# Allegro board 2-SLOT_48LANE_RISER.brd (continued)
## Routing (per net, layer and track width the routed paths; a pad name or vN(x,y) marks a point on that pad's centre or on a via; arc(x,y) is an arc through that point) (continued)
PE_SLOT2_RX_DN<11>: length 111.2
  IN2 w0.089: 142.12,92.72 142.09,92.75 141.07,92.75 141.03,92.7 140.98,92.66 140.63,92.66 140.58,92.7 140.54,92.75 140.18,92.75 140.14,92.7 140.09,92.66 139.74,92.66 139.69,92.7 139.65,92.75 138.88,92.75 v5(138.49,92.36)
  IN2 w0.145: 142.12,92.72 142.13,92.72 143.21,92.91 144.53,92.68 147.87,93.27 148,93.18 148.72,93.31 148.83,93.47 149.35,93.56 149.53,93.43 150.21,93.56 150.34,93.73 150.86,93.83 151.02,93.71 151.73,93.84 151.84,94 152.39,94.1 156.86,93.31 161.44,94.14 161.66,94.18 167.56,93.14 168.39,92.55 169.17,92.42 169.25,92.31 169.9,92.19 170.01,92.27 185.24,89.58 194.7,91.25 195.12,91.18 196.8,90.88 196.9,90.74 197.57,90.62 197.71,90.72 198.28,90.62 198.37,90.5 199.07,90.38 199.19,90.46 199.76,90.36 199.86,90.21 200.52,90.1 200.67,90.2 201.24,90.1 201.35,89.93 201.98,89.82 202.14,89.94 206.35,89.2 211.63,90.13 218.05,89 218.18,88.81 218.84,88.7 219.02,88.83 219.59,88.73 219.7,88.57 220.41,88.45 220.56,88.55 221.13,88.45 221.24,88.3 221.94,88.17 222.1,88.28 222.67,88.18 222.77,88.04 223.5,87.91 223.64,88.01 224.21,87.91 224.32,87.75 225.02,87.63 225.18,87.74 226.84,87.45 228.7,86.15 229.67,84.77 229.67,82.54 230.02,82.18 231.79,82.18 231.93,82.04 231.93,81.67 231.79,81.53 230.13,81.53 229.69,81.1 229.69,79.87 230.68,78.88 230.68,75.3 230.54,75.16 230.4,75.08 230.2,75.15 J2.A65
  BOTTOM w0.135: U1.D19 v5(138.49,92.36)
PE_SLOT2_RX_DN<12>: length 103.4
  IN2 w0.089: v5(138.49,90.76) 138.7,90.97 139.7,90.97 140.18,91.05 141.09,91.69 141.72,91.69 142.25,91.33 143.22,91.33 143.26,91.28 143.28,91.28
  IN2 w0.145: J2.A69 226.2,75.15 226.4,75.08 226.54,75.16 226.68,75.3 226.68,78.88 225.69,79.87 225.69,81.12 225.96,82.63 225.49,85.25 224.75,86.31 224.75,86.31 224.01,86.83 221.34,87.3 221.2,87.2 220.56,87.31 220.47,87.45 219.9,87.55 219.75,87.45 219.13,87.56 219.03,87.7 218.46,87.81 218.33,87.71 217.68,87.83 217.59,87.96 217.02,88.06 216.87,87.96 216.25,88.07 216.15,88.21 215.58,88.31 215.44,88.22 214.8,88.33 214.71,88.47 211.17,89.09 205.94,88.17 204.56,88.41 204.45,88.33 203.72,88.46 203.64,88.57 203.07,88.67 202.95,88.59 202.23,88.72 202.15,88.84 201.58,88.94 201.45,88.85 200.75,88.97 200.65,89.1 200.08,89.2 199.97,89.12 199.24,89.25 199.16,89.36 198.59,89.46 198.48,89.38 197.75,89.51 197.67,89.63 197.1,89.73 196.95,89.62 196.34,89.73 196.24,89.88 194.6,90.17 185.14,88.5 167.86,91.55 167.16,92.04 161.41,93.06 159.89,92.79 159.78,92.64 159.11,92.52 158.96,92.62 158.39,92.52 158.3,92.4 157.59,92.27 157.46,92.36 156.84,92.25 153.24,92.89 149.28,92.19 149.21,92.08 148.52,91.96 148.41,92.04 147.84,91.93 147.76,91.81 147.09,91.7 146.97,91.78 146.4,91.68 146.3,91.54 145.66,91.43 145.53,91.53 144.14,91.28 143.28,91.28
  BOTTOM w0.135: U1.D17 v5(138.49,90.76)
PE_SLOT2_RX_DN<13>: length 101.5
  IN2 w0.089: v5(138.49,89.96) 138.88,90.35 141.78,90.35 141.83,90.3 141.85,90.3
  IN2 w0.145: J2.A73 222.2,75.15 222.4,75.08 222.54,75.16 222.68,75.3 222.68,78.88 221.71,79.86 221.71,82.28 221.16,85.36 220.83,85.83 220.06,86.37 218.85,86.58 218.84,86.58 218.69,86.48 218.12,86.58 218.01,86.73 217.56,86.81 217.55,86.8 217.38,86.68 216.85,86.78 216.72,86.96 216.28,87.04 216.27,87.03 216.11,86.92 215.55,87.02 215.44,87.19 214.99,87.27 214.98,87.26 214.81,87.14 214.27,87.24 214.15,87.41 213.71,87.49 213.56,87.39 212.97,87.5 212.86,87.64 212.42,87.72 212.27,87.61 211.69,87.71 211.58,87.87 210.52,88.05 205.36,87.14 200.11,88.07 199.99,87.99 199.47,88.08 199.39,88.2 198.96,88.27 198.83,88.18 198.34,88.27 198.25,88.4 197.82,88.47 197.72,88.4 197.18,88.49 197.11,88.6 196.68,88.67 196.58,88.6 196.04,88.69 195.97,88.8 194.13,89.12 194.03,89.14 184.88,87.53 173.19,89.59 172.97,89.43 172.89,88.97 172.48,88.68 171.99,88.77 171.7,89.18 171.78,89.64 171.62,89.86 171.36,89.91 171.14,89.76 171.05,89.29 170.64,89 170.15,89.09 169.86,89.5 169.94,89.97 169.79,90.19 167.35,90.62 166.4,91.29 161.99,92.06 160.11,91.73 160.01,91.59 159.32,91.47 159.17,91.57 158.56,91.46 158.46,91.32 157.76,91.19 157.63,91.29 156.92,91.17 153.62,91.75 150.4,91.18 150.31,91.05 149.66,90.93 149.52,91.03 148.95,90.93 148.89,90.83 148.17,90.7 148.08,90.77 147.51,90.67 147.43,90.56 146.74,90.44 146.63,90.52 146.06,90.42 145.97,90.29 145.3,90.17 145.18,90.26 144.23,90.09 143.03,90.3 141.85,90.3
  BOTTOM w0.135: U1.D16 v5(138.49,89.96)
PE_SLOT2_RX_DN<14>: length 92.5
  IN2 w0.089: 141.73,89.25 141.72,89.25 141.71,89.26 141.68,89.3 141.19,89.39 140.6,89.24 139.75,88.65 139.31,88.57 138.7,88.57 v5(138.49,88.36)
  IN2 w0.145: J2.A77 218.2,75.15 218.4,75.08 218.54,75.16 218.68,75.3 218.68,78.88 217.7,79.86 217.7,80.52 217.55,81.36 217.12,81.97 216.16,82.65 216.03,82.7 216.02,82.7 214.91,83.17 212.8,84.64 212.8,84.65 210.82,85 210.7,84.91 210.01,85.03 209.92,85.15 209.35,85.25 209.25,85.18 208.52,85.31 208.45,85.41 207.88,85.51 207.79,85.45 207.05,85.58 206.98,85.67 204.62,86.09 204.52,86.02 203.83,86.14 203.76,86.24 203.19,86.34 203.07,86.26 202.41,86.37 202.33,86.49 201.76,86.59 201.66,86.52 200.96,86.65 200.89,86.74 200.32,86.85 200.22,86.77 199.53,86.9 199.46,87 198.89,87.1 198.82,87.05 198.08,87.18 198.03,87.25 197.46,87.35 197.37,87.29 196.66,87.42 196.6,87.5 196.03,87.6 195.92,87.53 195.24,87.65 195.17,87.75 193.66,88.02 190.4,87.44 189.62,86.33 185,85.51 170.04,88.15 167.95,89.61 164.95,90.14 164.83,90.06 164.27,90.16 164.18,90.28 163.28,90.44 163.17,90.36 162.54,90.47 162.47,90.58 161.48,90.75 161.28,90.75 161.27,90.75 161.13,90.75 156.86,90 153.35,90.62 151.63,90.31 151.55,90.2 150.96,90.1 150.85,90.18 150.49,90.11 150.39,89.97 149.85,89.88 149.71,89.97 149.35,89.91 149.24,89.75 148.73,89.66 148.57,89.77 148.21,89.71 148.11,89.57 147.57,89.48 147.43,89.57 147.07,89.51 146.98,89.39 146.41,89.29 146.29,89.37 145.93,89.31 145.82,89.16 145.3,89.06 145.15,89.17 144.15,88.99 143.28,89.09 141.73,89.25
  BOTTOM w0.135: U1.D14 v5(138.49,88.36)
PE_SLOT2_RX_DN<15>: length 90.1
  IN2 w0.089: 142.3,87.9 142.27,87.9 142.23,87.95 141.52,87.95 141.47,87.9 141.42,87.85 141.03,87.85 140.98,87.9 140.93,87.95 140.54,87.95 140.49,87.9 140.44,87.85 140.05,87.85 140,87.9 139.95,87.95 138.88,87.95 v5(138.49,87.56)
  IN2 w0.145: J2.A81 214.2,75.15 214.4,75.08 214.54,75.16 214.68,75.3 214.68,78.88 213.67,79.89 213.67,81.36 213.54,82.06 212.79,83.13 211.98,83.7 208.63,84.29 208.54,84.23 207.97,84.33 207.91,84.42 207.49,84.49 207.38,84.41 206.84,84.51 206.76,84.62 206.35,84.69 206.25,84.62 205.7,84.72 205.62,84.82 205.21,84.89 205.1,84.82 204.56,84.91 204.48,85.02 204.07,85.1 203.95,85.01 203.42,85.11 203.34,85.22 202.93,85.3 202.81,85.22 202.28,85.31 202.2,85.42 201.79,85.5 201.65,85.4 201.16,85.48 201.06,85.63 198.12,86.14 193,85.32 192.65,85.57 190.24,85.18 189.99,84.83 186.8,84.32 172.11,86.91 171.99,86.82 171.46,86.91 171.37,87.04 170.62,87.17 170.51,87.1 169.96,87.19 169.88,87.3 169.32,87.4 168.51,87.97 167.8,88.46 165.66,88.84 165.44,88.69 165.31,87.97 164.9,87.68 164.4,87.77 164.12,88.18 164.24,88.9 164.09,89.12 162.06,89.48 161.87,89.47 161.86,89.47 161.86,89.47 161.72,89.47 160.93,89.47 160.03,89.31 159.94,89.19 159.27,89.07 159.15,89.15 158.57,89.05 158.48,88.92 157.82,88.8 157.69,88.9 156.72,88.72 153.21,89.34 150.9,88.94 150.82,88.82 150.3,88.73 150.18,88.81 149.76,88.73 149.69,88.63 149.15,88.53 149.04,88.61 148.62,88.53 148.54,88.42 148.02,88.32 147.9,88.41 147.48,88.33 147.4,88.21 146.88,88.12 146.76,88.21 146.34,88.13 146.25,88.01 145.74,87.92 145.62,88 144.34,87.78 142.74,87.9 142.74,87.9 142.3,87.9
  BOTTOM w0.135: U1.D13 v5(138.49,87.56)
PE_SLOT2_RX_DP<0>: length 181
  IN2 w0.089: 126.09,96.01 126.09,95.98 126.12,95.94 126.11,95.8 126.11,92.74 v5(126.49,92.36)
  IN2 w0.145: 126.09,96.01 126.22,97.49 126.38,99.25 126.38,99.25 126.42,99.71 129.14,103.59 132.59,106.01 137.47,106.87 141.74,109.86 151.92,111.65 152.06,111.65 152.07,111.65 153.74,111.65 165.35,109.6 167.5,108.1 173.46,103.93 190.58,100.91 194.05,101.52 206.66,99.29 212.11,100.25 272.94,89.53 272.94,89.53 273.77,89.38 276.02,87.95 277.98,85.14 278.35,83.07 277.95,80.82 277.95,79.96 278.94,78.98 278.94,75.16 278.7,74.93 278.52,74.84 278.46,74.64 J2.A16
  BOTTOM w0.135: U1.V19 v5(126.49,92.36)
PE_SLOT2_RX_DP<1>: length 180.4
  IN2 w0.089: v5(127.29,92.36) 126.91,92.74 126.91,93.47 126.67,93.71 126.67,94.24 127.22,95.02 127.27,95.14 127.25,95.2 127.26,95.22
  IN2 w0.145: 127.26,95.22 127.3,95.33 127.4,95.91 127.32,96.39 127.95,99.98 129.65,102.41 132.94,104.71 144.49,106.75 145.55,106.56 145.82,106.75 146.08,108.23 146.44,108.48 147.03,108.38 147.28,108.02 147.02,106.54 147.17,106.32 147.44,106.27 147.66,106.42 147.92,107.91 148.28,108.16 148.86,108.06 149.11,107.7 148.85,106.21 149.01,105.99 152.28,105.41 152.28,105.42 162.9,107.29 168.39,106.32 173.01,103.08 190.63,99.98 194.35,100.63 206.77,98.44 212.25,99.41 267.6,89.65 270.47,89.15 273.25,87.2 273.8,86.42 273.94,85.6 273.94,79.76 272.97,78.78 272.97,75.31 273.12,75.16 273.26,75.08 273.46,75.15 J2.A21
  BOTTOM w0.124: U1.U19 v5(127.29,92.36)
PE_SLOT2_RX_DP<2>: length 167
  IN2 w0.089: 128.47,96.34 128.47,96.32 128.51,96.28 128.51,92.74 v5(128.89,92.36)
  IN2 w0.145: J2.A25 269.46,75.15 269.26,75.08 269.12,75.16 269,75.28 269,78.81 269.94,79.76 269.94,80.77 270.32,82.89 269.89,85.34 268.74,86.97 265.58,89.18 212.46,98.55 206.59,97.51 194.25,99.69 194.21,99.69 189.99,98.95 172.14,102.09 167.88,105.07 162.14,106.08 152.03,104.3 144.39,105.65 133.4,103.72 130.38,101.6 129.02,99.66 128.47,96.51 128.47,96.34
  BOTTOM w0.135: U1.R19 v5(128.89,92.36)
PE_SLOT2_RX_DP<3>: length 164.7
  IN2 w0.089: 129.54,95.89 129.54,95.87 129.57,95.82 129.49,95.35 129.11,94.81 129.07,94.58 129.07,93.51 129.31,93.27 129.31,92.74 v5(129.69,92.36)
  IN2 w0.145: 129.54,95.89 130.16,99.4 131.29,101.01 133.59,102.62 144.47,104.54 152.52,103.12 161.78,104.75 162.13,104.75 167.3,103.84 171.28,101.05 175.25,100.35 175.54,99.94 175.49,99.7 175.65,99.48 175.91,99.43 176.14,99.59 176.18,99.83 176.59,100.12 177.08,100.03 177.37,99.62 177.33,99.38 177.48,99.15 177.75,99.11 177.97,99.26 178.02,99.5 178.43,99.79 178.92,99.7 179.21,99.29 179.17,99.05 179.32,98.83 179.59,98.78 179.81,98.94 179.85,99.18 180.26,99.47 180.76,99.38 181.05,98.97 181,98.73 181.16,98.51 181.43,98.46 181.65,98.61 181.69,98.86 182.1,99.14 189.82,97.78 194.57,98.62 206.46,96.53 212.87,97.66 260.95,89.18 264.61,86.61 265.94,84.71 265.94,79.76 264.97,78.78 264.97,75.31 265.12,75.16 265.17,75.13 265.5,75.24 J2.A29
  BOTTOM w0.135: U1.P19 v5(129.69,92.36)
PE_SLOT2_RX_DP<4>: length 154.2
  IN2 w0.145: J2.A35 259.46,75.15 259.26,75.08 259.12,75.16 258.99,75.29 258.99,78.8 259.94,79.76 259.94,85.54 259.6,87.48 259.03,88.3 258.27,88.83 213,96.82 206.24,95.62 194.57,97.68 187.59,96.45 185.02,96.9 185.02,96.9 171.64,99.26 166.74,102.7 162.85,103.38 160.32,103.38 160.32,103.38 160.17,103.38 152.56,102.04 146.79,103.06 136.93,101.32 136.81,101.27 135.39,100.28 134.71,100.16 133.84,100.31 132.61,100.1 132.16,99.78 131.17,98.36 131.14,98.17 131.12,98.11 131.12,93 131.51,92.62 131.83,92.62 v5(132.09,92.36)
  BOTTOM w0.124: U1.M19 v5(132.09,92.36)
PE_SLOT2_RX_DP<5>: length 153.8
  IN2 w0.089: v5(132.89,92.36) 132.51,92.74 132.51,93.27 131.98,93.8 131.98,95.55 132.4,96.59 132.38,96.65 132.39,96.67
  IN2 w0.145: J2.A39 255.46,75.15 255.26,75.08 255.12,75.16 254.97,75.3 254.97,78.79 255.94,79.76 255.94,86.13 255.73,87.34 255.23,88.06 254.51,88.57 212.78,95.92 206.16,94.75 194.55,96.8 187.09,95.48 177.83,97.12 171.49,98.24 166.36,101.83 162.42,102.52 158.38,101.81 149.61,100.26 149.39,100.42 149.18,101.63 148.82,101.88 148.23,101.78 147.98,101.42 148.2,100.21 148.04,99.98 147.78,99.94 147.55,100.09 147.25,101.8 146.84,102.09 146.35,102 146.06,101.59 146.36,99.88 146.2,99.66 145.47,99.53 140.44,100.42 138.63,100.1 136.21,98.4 135.12,98.23 133.92,98.02 132.79,97.23 132.39,96.67
  BOTTOM w0.135: U1.L19 v5(132.89,92.36)
PE_SLOT2_RX_DP<6>: length 140.4
  IN2 w0.089: v5(134.49,92.36) 134.11,92.74 134.11,93.33 133.46,93.99 133.46,95.53 133.41,95.58 133.41,95.6
  IN2 w0.145: J2.A43 251.46,75.15 251.26,75.08 251.12,75.16 251,75.27 251,78.81 251.94,79.76 251.94,85.37 251.69,86.84 251.13,87.64 249.78,88.58 213.26,95.02 206.43,93.81 194.3,95.91 186.58,94.55 171.09,97.28 166.02,100.83 163.39,101.29 160.82,101.29 160.82,101.29 160.67,101.29 154.43,100.19 142.95,98.17 142.2,98.04 141.45,98.17 140.35,98.37 139.22,98.17 138.78,98.09 138.77,98.09 134.56,97.35 133.93,96.91 133.49,96.28 133.41,95.83 133.41,95.6
  BOTTOM w0.135: U1.J19 v5(134.49,92.36)
PE_SLOT2_RX_DP<7>: length 140.3
  IN2 w0.089: v5(135.29,92.36) 135.29,92.63 134.91,93.01 134.91,94.76 134.93,94.89 134.89,94.94 134.89,94.96
  IN2 w0.145: 134.89,94.96 134.95,95.61 135.38,96.23 136.15,96.77 139.74,97.4 142.32,96.95 143.28,97.12 156.82,99.5 157.22,99.22 157.5,97.63 157.67,97.51 158.03,97.57 158.15,97.74 157.87,99.33 158.15,99.74 158.65,99.83 159.06,99.54 159.35,97.92 159.51,97.8 159.87,97.87 159.99,98.03 159.7,99.66 159.99,100.07 160.83,100.22 166.65,99.19 170.88,96.23 186.17,93.53 194.57,95.01 206.22,92.96 213.26,94.2 244.55,88.68 245.68,87.89 247.04,85.95 247.96,80.77 247.96,79.83 246.97,78.84 246.97,75.31 247.12,75.16 247.26,75.08 247.46,75.15 J2.A47
  BOTTOM w0.135: U1.H19 v5(135.29,92.36)
PE_SLOT2_RX_DP<8>: length 121.2
  IN2 w0.145: J2.A52 242.46,74.64 242.52,74.84 242.7,74.93 242.95,75.18 242.95,79.02 241.97,80 241.97,85.73 240.33,88.08 236.63,88.73 236.2,89.34 234.64,89.61 213.26,93.38 206.22,92.14 194.68,94.17 186.17,92.67 172.45,95.09 172.45,95.09 170.28,95.48 168.14,96.97 164.24,97.66 160.87,97.07 157.59,96.49 151.49,97.57 143.28,96.12 142.55,95.99 141.35,96.2 138.52,96.2 137.88,95.56 v5(137.69,95.56)
  BOTTOM w0.135: U1.E23 v5(137.69,95.56)
PE_SLOT2_RX_DP<9>: length 119.8
  IN2 w0.089: 141.72,95.38 141.7,95.38 141.66,95.34 138.8,95.34 138.62,95.16 138.25,95.16 v5(137.69,94.76)
  IN2 w0.145: 141.72,95.38 141.89,95.38 143.28,95.14 143.29,95.14 143.43,95.14 143.43,95.14 151.93,96.63 151.93,96.63 157.68,95.62 163.8,96.7 164.52,96.7 167.82,96.11 170.09,94.53 185.82,91.76 194.79,93.34 194.87,93.32 206.22,91.32 212.7,92.47 229.75,89.46 230.37,89.35 231.05,88.87 232.15,88.11 236.04,87.42 236.89,86.83 237.72,85.64 237.95,84.34 237.95,83.2 238.14,83.01 239.6,83.01 239.96,82.66 239.96,82.15 239.6,81.8 238.14,81.8 237.95,81.61 237.95,80.04 238.97,79.01 238.97,75.19 238.7,74.93 238.52,74.84 238.51,74.83 238.45,74.65 J2.A56
  BOTTOM w0.135: U1.E22 v5(137.69,94.76)
PE_SLOT2_RX_DP<10>: length 112.1
  IN2 w0.089: v5(137.69,93.16) 138.25,93.56 138.62,93.56 138.8,93.74 139.16,93.74 139.75,93.84 140.33,94.25 140.85,94.34 140.98,94.36 141.02,94.41 141.04,94.42
  IN2 w0.145: 141.04,94.42 141.89,94.57 143.28,94.32 144.24,94.15 151.61,95.45 151.98,95.52 152.58,95.62 157.54,94.75 160.4,95.25 162.72,95.66 163.12,95.59 164.35,95.37 167.71,94.78 169.28,93.68 185.44,90.83 194.63,92.45 206.13,90.42 212.42,91.53 227.13,88.94 228.95,87.67 232.23,87.09 233.17,86.43 233.44,86.05 233.73,84.41 233.65,83.98 233.83,82.96 234.01,81.95 234.01,79.95 234.94,79.02 234.94,75.17 234.7,74.93 234.58,74.87 234.49,74.58 J2.A60
  BOTTOM w0.135: U1.E20 v5(137.69,93.16)
PE_SLOT2_RX_DP<11>: length 111.3
  IN2 w0.089: v5(137.69,92.36) 138.25,92.76 138.62,92.76 138.8,92.94 142.03,92.94 142.03,92.94 142.05,92.94 142.11,93
  IN2 w0.145: J2.A64 230.45,74.65 230.51,74.83 230.7,74.93 230.96,75.19 230.96,78.99 229.97,79.98 229.97,80.98 230.24,81.25 231.9,81.25 232.21,81.56 232.21,82.15 231.9,82.46 230.14,82.46 229.95,82.65 229.95,84.85 228.9,86.35 226.95,87.71 211.63,90.41 206.35,89.48 195.12,91.46 194.7,91.54 185.24,89.87 169.22,92.69 168.5,92.82 167.67,93.4 161.65,94.47 161.39,94.41 156.86,93.59 152.39,94.38 144.45,92.98 143.28,93.18 143.21,93.2 142.11,93
  BOTTOM w0.135: U1.E19 v5(137.69,92.36)
PE_SLOT2_RX_DP<12>: length 103.5
  IN2 w0.089: 143.28,91.56 143.26,91.56 143.22,91.52 142.31,91.52 141.78,91.88 141.03,91.88 140.1,91.23 139.69,91.16 138.25,91.16 v5(137.69,90.76)
  IN2 w0.145: J2.A68 226.46,74.64 226.52,74.84 226.7,74.93 226.96,75.19 226.96,78.99 225.97,79.99 225.97,81.1 226.24,82.63 225.76,85.36 224.95,86.51 224.12,87.09 211.17,89.37 205.94,88.45 194.6,90.45 185.14,88.78 176.56,90.3 167.97,91.81 167.26,92.31 161.41,93.34 159.84,93.06 156.84,92.53 153.24,93.17 144.11,91.56 143.28,91.56
  BOTTOM w0.135: U1.E17 v5(137.69,90.76)
PE_SLOT2_RX_DP<13>: length 101.5
  IN2 w0.089: 141.85,90.58 141.83,90.58 141.78,90.54 138.8,90.54 138.62,90.36 138.25,90.36 v5(137.69,89.96)
  IN2 w0.145: J2.A72 222.46,74.64 222.52,74.84 222.7,74.93 222.96,75.19 222.96,78.99 221.99,79.97 221.99,82.3 221.43,85.47 221.03,86.03 220.17,86.64 210.52,88.34 205.36,87.43 194.13,89.41 194.03,89.43 184.88,87.81 173.13,89.88 172.72,89.59 172.64,89.13 172.41,88.97 172.15,89.02 171.99,89.24 172.08,89.71 171.79,90.12 171.29,90.21 170.88,89.92 170.8,89.45 170.58,89.3 170.31,89.34 170.16,89.57 170.24,90.03 169.95,90.44 167.46,90.88 166.51,91.55 161.99,92.35 159.95,91.99 159.24,91.86 159.24,91.86 156.92,91.45 153.62,92.03 144.22,90.38 143.28,90.54 143.05,90.58 141.85,90.58
  BOTTOM w0.135: U1.E16 v5(137.69,89.96)
PE_SLOT2_RX_DP<14>: length 92.6
  IN2 w0.089: 141.76,89.53 141.74,89.53 141.69,89.49 141.56,89.52 141.19,89.58 140.52,89.42 139.67,88.83 139.29,88.76 138.25,88.76 v5(137.69,88.36)
  IN2 w0.145: 141.76,89.53 143.28,89.37 144.14,89.28 153.35,90.9 156.86,90.28 161.13,91.04 161.27,91.04 161.28,91.03 161.51,91.03 168.06,89.88 170.15,88.42 185,85.8 189.45,86.58 190.24,87.7 193.66,88.3 212.91,84.91 215.05,83.41 216.13,82.96 216.13,82.96 216.27,82.91 217.32,82.17 217.81,81.47 217.98,80.55 217.98,79.98 218.96,78.99 218.96,75.19 218.7,74.93 218.52,74.84 218.46,74.64 J2.A76
  BOTTOM w0.135: U1.E14 v5(137.69,88.36)
PE_SLOT2_RX_DP<15>: length 90.2
  IN2 w0.089: 142.3,88.18 142.27,88.18 142.23,88.14 138.8,88.14 138.62,87.96 138.25,87.96 v5(137.69,87.56)
  IN2 w0.145: J2.A80 214.46,74.64 214.52,74.84 214.7,74.93 214.96,75.19 214.96,78.99 213.95,80.01 213.95,81.38 213.81,82.17 212.99,83.33 212.09,83.97 198.12,86.43 193.06,85.61 192.72,85.86 190.08,85.44 189.83,85.09 186.8,84.6 172.16,87.18 169.43,87.67 167.91,88.73 165.59,89.14 165.18,88.85 165.05,88.13 164.83,87.97 164.57,88.02 164.41,88.24 164.54,88.96 164.25,89.37 162.09,89.76 161.86,89.75 161.85,89.75 161.71,89.75 160.93,89.75 160.88,89.74 156.72,89.01 153.21,89.63 144.32,88.06 142.78,88.18 142.76,88.18 142.3,88.18
  BOTTOM w0.135: U1.E13 v5(137.69,87.56)
PE_SLOT2_TX_C_DN<0>: length 178.1
  BOTTOM w0.089: U1.V23 126.83,95.16 126.58,95.41 126.58,96.16 126.64,96.22 126.64,96.24
  BOTTOM w0.135: C43.1 279.68,85.46 279.68,85.83 279.4,86.23 279.24,86.26 279,86.61 279.02,86.77 278.64,87.32 277.69,87.98 277.49,87.94 277.06,88.24 277.02,88.45 276.58,88.75 276.39,88.72 275.95,89.03 275.92,89.22 275.48,89.53 275.29,89.5 274.85,89.8 274.81,89.99 274.37,90.3 274.18,90.27 273.74,90.58 273.71,90.77 273.27,91.08 273.08,91.04 272.64,91.35 272.6,91.54 272.16,91.85 271.97,91.82 271.53,92.13 271.5,92.32 v8(267.05,95.43) 264.62,97.13 249.04,99.88 246.56,101.61 216.77,106.86 202.91,104.42 196.3,105.59 180.42,102.79 174.43,103.84 172.19,105.41 168.51,110.67 164.08,113.77 154.9,115.39 154.71,115.26 154.2,115.35 154.07,115.53 153.54,115.63 153.36,115.5 152.85,115.59 152.72,115.77 152.19,115.87 150.1,116.23 140.15,114.48 137.3,112.49 137.25,112.44 130.4,105.58 130.4,105.38 130.04,105.02 129.84,105.02 129.52,104.71 129.52,104.5 129.16,104.14 128.96,104.14 128.65,103.83 128.65,103.65 128.26,103.26 128.08,103.26 127.77,102.95 127.77,102.75 127.41,102.39 127.2,102.39 126.37,101.55 126.37,100.02 126.49,99.89 126.49,99.3 126.37,99.18 126.37,98.64 126.49,98.51 126.49,97.92 126.37,97.8 126.37,97.33 126.64,97.06 126.64,96.24
PE_SLOT2_TX_C_DN<1>: length 176
  BOTTOM w0.089: U1.U23 127.61,95.16 127.5,95.27 127.5,96.95 127.55,97 127.55,97.02
  BOTTOM w0.135: 127.55,97.02 127.55,97.33 127.84,97.61 127.84,101.07 128.53,101.75 128.63,101.75 128.73,101.75 129.11,102.13 129.11,102.23 129.11,102.23 129.11,102.34 129.49,102.72 129.59,102.72 129.59,102.72 129.69,102.72 130.07,103.1 130.07,103.2 130.07,103.2 130.07,103.3 130.45,103.68 130.56,103.68 130.56,103.68 130.66,103.68 131.04,104.06 131.04,104.16 131.04,104.16 131.04,104.26 131.42,104.65 131.52,104.65 131.52,104.64 131.62,104.64 132,105.03 132,105.13 132,105.23 132.38,105.61 132.48,105.61 132.59,105.61 132.97,105.99 132.97,106.09 132.97,106.19 138.75,111.98 142.2,113.4 142.93,113.53 143.1,113.41 143.63,113.5 143.75,113.67 149.91,114.76 150.86,114.59 150.98,114.42 151.51,114.33 151.68,114.44 152.21,114.35 152.32,114.18 152.85,114.09 153.02,114.21 153.55,114.11 153.67,113.95 154.2,113.85 154.36,113.97 154.89,113.87 155.01,113.71 155.54,113.61 155.7,113.73 155.71,113.73 155.85,113.7 155.86,113.71 162.57,112.52 168.49,108.38 171.07,104.7 173.95,102.68 180.48,101.53 195.81,104.24 202.75,103.01 217.06,105.53 245.38,100.54 247.9,98.77 249.41,98.51 249.51,98.36 250.11,98.26 250.25,98.36 250.78,98.26 250.87,98.14 251.5,98.03 251.63,98.11 252.16,98.02 252.26,97.87 252.85,97.77 253,97.87 253.53,97.78 253.63,97.63 254.22,97.52 254.37,97.63 254.9,97.54 255.01,97.38 255.59,97.28 255.74,97.39 v8(260.15,96.61) 262.91,96.19 268.04,92.6 268.11,92.19 267.83,91.79 267.92,91.28 268.34,90.98 268.85,91.07 269.13,91.47 269.4,91.52 269.62,91.36 269.66,91.1 269.38,90.7 269.47,90.19 269.9,89.89 270.41,89.98 270.69,90.38 270.95,90.43 271.17,90.28 271.21,90.02 270.93,89.61 271.02,89.1 271.45,88.8 271.96,88.89 272.24,89.3 272.5,89.34 273.59,88.58 273.62,88.43 274.13,88.07 274.28,88.1 275.19,87.47 275.64,86.81 275.64,85.46 C44.1
PE_SLOT2_TX_C_DN<2>: length 164.7
  BOTTOM w0.089: U1.R23 129.21,95.16 129.1,95.27 129.1,96.95 129.16,97 129.16,97.02
  BOTTOM w0.135: 129.16,97.02 129.16,100.45 129.59,100.89 129.69,100.89 129.79,100.89 130.18,101.27 130.18,101.37 130.18,101.47 130.56,101.85 130.66,101.85 130.76,101.85 131.14,102.23 131.14,102.33 131.14,102.44 131.52,102.82 131.62,102.82 131.72,102.82 132.1,103.2 132.1,103.3 132.1,103.4 132.48,103.78 132.59,103.78 132.69,103.78 133.07,104.16 133.07,104.26 133.07,104.36 133.95,105.25 134.18,105.25 134.59,105.65 134.59,105.88 136.6,107.89 136.85,107.89 137.41,108.45 137.41,108.71 138.53,109.83 141.09,111.62 150.1,113.21 150.77,113.09 150.9,112.9 151.51,112.8 151.69,112.93 152.22,112.83 152.34,112.66 152.97,112.55 153.14,112.67 153.67,112.58 153.79,112.4 154.41,112.29 154.59,112.42 155.12,112.32 155.23,112.15 155.87,112.04 156.03,112.16 162.49,111.02 167.59,107.45 170.11,103.86 173.61,101.4 180.22,100.24 195.87,103 203.26,101.7 217.28,104.17 244.84,99.31 247.86,97.19 v8(252.86,96.31) 259.73,95.1 263.17,92.69 263.21,92.49 263.57,92.23 263.77,92.27 264.13,92.02 264.17,91.82 264.53,91.56 264.73,91.6 266.39,90.43 266.43,90.23 266.87,89.92 267.08,89.95 267.52,89.64 267.55,89.44 268,89.13 268.2,89.17 268.64,88.86 268.68,88.65 269.12,88.34 269.33,88.38 271.29,87 271.67,86.55 271.71,86.44 271.71,85.46 C45.1
PE_SLOT2_TX_C_DN<3>: length 162.6
  BOTTOM w0.089: 129.95,97.02 129.95,97 129.9,96.95 129.9,95.27 130.01,95.16 U1.P23
  BOTTOM w0.135: C46.1 267.37,85.11 267.67,85.41 267.67,86.01 267.49,86.99 266.94,87.78 266.55,88.06 266.08,87.97 265.45,87.08 264.94,86.99 264.52,87.28 264.43,87.79 264.97,88.56 264.92,88.83 264.7,88.98 264.44,88.94 264.13,88.49 263.62,88.4 263.19,88.7 263.1,89.21 263.41,89.65 263.37,89.88 262.48,90.51 262.28,90.47 261.84,90.78 261.81,90.98 261.36,91.29 261.17,91.25 260.73,91.56 260.69,91.76 260.25,92.07 260.06,92.03 259.61,92.35 259.58,92.54 259.13,92.85 258.94,92.81 258.5,93.12 258.46,93.32 257.11,94.26 246.28,96.17 243.32,98.25 241.47,98.58 241.28,98.45 240.75,98.54 240.62,98.72 240.09,98.82 239.91,98.69 239.38,98.78 239.25,98.97 238.72,99.06 238.53,98.93 237.98,99.03 237.85,99.22 217.35,102.85 203.26,100.36 195.71,101.69 180.35,98.99 173.06,100.27 168.83,103.23 166.52,106.53 162.08,109.64 149.51,111.86 147.43,111.24 146.53,110.98 v8(145.89,110.79) 144.65,110.42 144.55,110.24 144,110.07 143.81,110.17 143.29,110.02 143.21,109.87 142.6,109.69 142.45,109.77 141.93,109.62 141.84,109.45 141.26,109.28 141.09,109.37 140.28,109.13 139.72,108.74 137.62,105.74 136.91,105.03 135.69,105.03 135.34,104.68 135.34,104.48 134.93,104.07 134.85,104.07 134.73,104.07 134.35,103.69 134.35,103.54 133.89,103.08 133.86,103.08 133.74,103.08 133.36,102.7 133.36,102.5 132.95,102.09 132.87,102.09 132.75,102.09 132.37,101.71 132.37,101.53 131.94,101.1 131.88,101.1 131.76,101.1 131.38,100.72 131.38,100.52 130.97,100.11 130.89,100.11 130.77,100.11 130.36,99.7 130.36,97.73 129.95,97.33 129.95,97.02
PE_SLOT2_TX_C_DN<4>: length 145.9
  BOTTOM w0.089: U1.M23 131.61,95.16 131.5,95.27 131.5,96.95 131.56,97 131.56,97.02
  BOTTOM w0.135: C115.1 261.67,85.46 261.67,86.11 261.45,86.55 260.64,87.94 258.71,89.85 257.82,90.38 257.61,90.33 257.03,90.68 256.98,90.89 256.51,91.16 256.34,91.12 255.71,91.49 255.67,91.67 255.21,91.95 255,91.9 254.42,92.25 254.37,92.45 253.9,92.73 253.71,92.68 253.11,93.04 253.06,93.23 252.52,93.56 252.26,93.6 252.25,93.6 252.08,93.47 251.55,93.55 251.42,93.72 250.89,93.81 250.72,93.68 250.19,93.76 250.06,93.93 249.53,94.02 249.36,93.89 248.83,93.97 248.7,94.14 248.17,94.22 248,94.1 247.47,94.18 247.34,94.35 246.63,94.46 242.81,96.94 216.17,101.28 216.17,101.28 203.18,98.91 195.02,100.35 180.21,97.74 172.67,99.07 167.9,102.41 161.74,103.49 v8(160.32,103.74) 147.09,106.07 145.89,105.97 145.75,105.81 145.23,105.76 145.07,105.9 144.59,105.86 144.47,105.71 143.98,105.67 143.83,105.79 143.24,105.74 143.11,105.59 142.58,105.54 142.43,105.67 141.89,105.62 141.76,105.47 141.23,105.42 141.08,105.55 139.11,105.38 137.36,103.63 136.2,103.63 135.41,102.85 135.41,102.75 135.41,102.64 135.03,102.26 134.93,102.26 134.83,102.26 134.45,101.88 134.45,101.78 134.45,101.68 134.07,101.3 133.97,101.3 133.86,101.3 133.48,100.92 133.48,100.82 133.48,100.82 133.48,100.72 133.1,100.33 133,100.33 133,100.34 132.9,100.34 132.52,99.95 132.52,99.85 132.52,99.85 132.52,99.75 132.14,99.37 132.04,99.37 132.04,99.37 131.94,99.37 131.56,99 131.56,97.02
PE_SLOT2_TX_C_DN<5>: length 145.6
  BOTTOM w0.089: 132.35,97.02 132.35,97 132.3,96.95 132.3,96.5 132.34,96.46 132.41,96.39 132.41,96.08 132.34,96.01 132.3,95.97 132.3,95.27 132.41,95.16 U1.L23
  BOTTOM w0.135: 132.35,97.02 132.35,97.33 132.84,97.82 133.1,97.82 134.04,98.76 134.27,98.76 134.62,99.11 134.62,99.34 135.13,99.85 135.36,99.85 135.74,100.23 135.74,100.46 136.12,100.84 136.35,100.84 136.73,101.22 136.73,101.45 137.47,102.19 139.23,103.42 139.88,103.54 140.05,103.42 140.58,103.51 140.71,103.68 141.24,103.78 141.41,103.66 141.94,103.75 142.06,103.92 142.59,104.02 142.76,103.89 143.29,103.99 143.42,104.16 143.95,104.26 144.12,104.13 144.65,104.23 144.77,104.4 145.3,104.49 145.47,104.37 146,104.47 146.12,104.64 147.11,104.81 v8(156,103.24) 157.52,102.97 159.77,102.58 159.88,102.43 160.48,102.32 160.63,102.43 161.16,102.33 161.27,102.16 161.84,102.06 162.01,102.18 162.54,102.09 162.65,101.93 163.24,101.83 163.4,101.94 163.93,101.84 164.03,101.7 164.64,101.59 164.78,101.69 167.34,101.24 172.07,97.93 180.23,96.5 195.03,99.1 196.64,98.82 196.65,98.82 196.7,98.81 198.44,98.5 198.56,98.33 198.99,98.26 199.16,98.38 199.59,98.3 199.71,98.13 200.14,98.05 200.31,98.17 203.53,97.6 216.21,99.84 238.97,95.83 244.75,93.77 246.56,92.94 247.18,92.76 247.35,92.43 246.92,91.02 247.22,90.47 247.82,90.29 248.37,90.59 248.79,91.99 249.12,92.17 249.48,92.06 249.65,91.73 249.23,90.33 249.52,89.78 250.12,89.6 250.67,89.89 251.09,91.3 251.42,91.47 252.41,91.17 256.41,88.24 257.45,87.2 257.63,86.18 257.63,85.46 C116.1
PE_SLOT2_TX_C_DN<6>: length 131.3
  BOTTOM w0.089: U1.J23 133.99,95.16 133.9,95.25 133.9,96.39 133.96,96.44 133.96,96.47
  BOTTOM w0.135: C117.1 253.67,85.46 253.67,85.92 253.41,86.29 253.18,86.45 252.43,86.87 252.23,86.81 251.76,87.07 251.71,87.26 251.23,87.52 251.04,87.47 250.57,87.73 250.51,87.92 249.98,88.21 247.65,88.62 247.42,88.78 247.2,88.74 246.76,89.05 246.73,89.27 246.28,89.58 246.07,89.54 245.63,89.85 245.59,90.06 245.15,90.37 244.94,90.33 244.49,90.64 244.46,90.86 244.02,91.17 243.8,91.13 243.36,91.44 243.32,91.65 242.88,91.96 242.67,91.92 242.23,92.23 242.19,92.45 241.75,92.76 241.53,92.72 241.09,93.03 241.05,93.24 240.25,93.8 239.8,93.99 215.51,98.27 203.72,96.19 194.58,97.81 180.23,95.27 175.92,96.03 171.6,96.8 167.15,99.91 165.37,100.22 165.37,100.22 164.64,100.35 163.16,100.61 v8(163.16,100.61) 162.63,100.7 161.26,100.95 161.13,100.86 160.51,100.97 160.42,101.09 159.89,101.19 159.75,101.09 159.15,101.2 159.05,101.34 147.24,103.42 146.09,103.22 145.96,103.04 145.43,102.94 145.25,103.07 144.72,102.98 144.59,102.79 144.06,102.7 143.88,102.83 141.93,102.48 140.82,101.71 139.79,101.52 139.29,101.02 139.29,100.86 139.29,100.78 138.83,100.32 138.59,100.32 138.21,99.94 138.21,99.73 137.73,99.25 137.52,99.25 137.14,98.87 137.14,98.68 136.63,98.17 136.44,98.17 136.24,97.97 135.28,97.97 134.83,97.53 134.83,97.39 134.53,97.09 134.39,97.09 133.96,96.66 133.96,96.47
PE_SLOT2_TX_C_DN<7>: length 131
  BOTTOM w0.089: 135.26,96.29 135.18,96.29 134.7,95.81 134.7,95.27 134.81,95.16 U1.H23
  BOTTOM w0.135: C118.1 249.63,85.46 249.63,85.89 249.5,86.02 248.69,86.02 248.39,85.72 248.39,84.21 248.08,83.89 247.21,83.89 246.83,84.28 246.83,86.44 246.73,86.71 246.14,87.41 245.8,87.75 244.81,88.44 244.61,88.41 244.25,88.66 244.22,88.86 243.86,89.11 243.65,89.08 243.29,89.33 243.26,89.53 242.06,90.37 241.8,90.32 241.51,89.9 241,89.81 240.57,90.11 240.48,90.62 240.77,91.04 240.73,91.3 240.04,92.28 238.52,92.89 238.51,92.89 238.39,92.94 238.39,92.94 237.01,93.18 237.01,93.18 235.87,93.38 235.71,93.27 235.28,93.35 235.17,93.51 235.16,93.51 233,93.89 230.39,94.35 230.21,94.23 229.78,94.3 229.65,94.48 229.22,94.56 229.04,94.43 228.61,94.51 228.48,94.69 226.76,94.99 226.6,94.88 226.11,94.97 226,95.13 225.57,95.2 225.41,95.09 224.92,95.18 224.81,95.34 222.25,95.79 222.25,95.79 221.68,95.89 221.1,95.99 221.1,95.99 215.41,96.99 203.42,94.88 194.72,96.41 180.52,93.91 171.14,95.56 166.83,98.57 157.04,100.3 v8(155.66,100.54) 154.72,100.71 154.56,100.6 154.03,100.69 153.92,100.85 153.39,100.94 153.23,100.83 152.7,100.93 152.58,101.09 152.05,101.18 151.89,101.07 151.36,101.16 151.25,101.32 150.72,101.42 150.56,101.3 150.03,101.4 149.92,101.56 149.38,101.65 149.22,101.54 148.69,101.63 148.58,101.79 147.31,102.02 146.12,101.81 145.98,101.61 145.45,101.52 145.25,101.66 144.14,101.46 143.65,101.46 142.83,100.89 142.8,100.72 142.23,100.32 142.06,100.35 141.42,99.9 141.17,99.86 141.16,99.86 140.15,99.86 138.49,98.21 138.49,98.03 138.01,97.55 137.83,97.55 137.29,97 135.97,97 135.26,96.29
PE_SLOT2_TX_C_DN<8>: length 112.1
  BOTTOM w0.135: C119.1 243.7,85.46 243.7,85.84 243.64,86.19 243.27,86.71 242.36,87.26 241.43,87.43 240.69,87.94 240.48,87.91 240.12,88.16 240.08,88.37 239.72,88.62 239.5,88.59 239.14,88.84 239.11,89.05 237.82,89.96 237.63,89.92 237.27,90.17 237.23,90.36 236.87,90.62 236.68,90.58 236.32,90.83 236.29,91.02 234.95,91.96 214.63,95.55 213.18,95.29 213.06,95.12 212.63,95.05 212.47,95.16 212.03,95.08 211.92,94.92 211.49,94.84 211.32,94.96 208.92,94.53 208.8,94.35 208.36,94.27 208.18,94.4 207.75,94.32 207.62,94.14 207.19,94.06 207,94.19 207,94.19 203.66,93.6 196.54,94.86 195.02,95.12 180.76,92.61 170.54,94.41 166.67,97.12 v8(157.04,98.82) 148.05,100.4 145.9,100.03 143.79,99.65 142.34,98.64 140.27,95.68 140.25,95.55 140.25,95.4 U1.A23
PE_SLOT2_TX_C_DN<9>: length 111.8
  BOTTOM w0.135: U1.A22 140.59,94.46 141.09,94.46 142.94,97.11 143.28,97.35 144.49,98.19 145.18,98.31 145.35,98.2 145.87,98.29 145.98,98.45 146.51,98.55 146.67,98.44 147.2,98.53 147.31,98.69 147.84,98.78 148,98.67 148.53,98.77 148.64,98.92 149.08,99 v8(153.39,98.24) 154.8,97.99 165.75,96.06 169.61,93.35 180.94,91.35 195.05,93.84 197.78,93.36 197.91,93.18 198.34,93.1 198.52,93.23 198.95,93.15 199.08,92.97 199.51,92.9 199.69,93.02 203.05,92.43 203.16,92.26 203.59,92.19 203.76,92.3 204.19,92.23 204.31,92.06 204.74,91.99 204.91,92.1 206.12,91.89 209.18,92.43 210.57,93.4 214.92,94.17 214.92,94.17 215.03,94.19 217.61,93.73 217.72,93.58 218.16,93.5 218.32,93.61 218.75,93.53 218.86,93.38 219.29,93.3 219.45,93.41 219.88,93.33 220,93.17 220.43,93.1 220.59,93.21 228.44,91.83 228.56,91.66 229.09,91.57 229.25,91.68 229.78,91.59 229.9,91.42 230.43,91.33 230.59,91.45 233.27,90.98 236.32,88.84 236.92,87.98 237.01,87.49 237.01,84.58 237.32,84.27 238.2,84.27 238.51,84.58 238.51,85.84 238.65,85.97 239.57,85.97 239.7,85.84 239.7,85.46 C120.1
PE_SLOT2_TX_C_DN<10>: length 103.7
  BOTTOM w0.135: C121.1 234.58,85.21 234.68,85.47 234.68,86.07 234.79,86.67 234.59,87.82 234.23,88.33 233.75,88.66 233.54,88.63 233,89.01 232.96,89.22 232.2,89.75 231.46,89.88 231.28,89.75 230.75,89.85 230.62,90.03 230.09,90.12 229.91,89.99 229.38,90.09 229.25,90.27 228.72,90.36 228.53,90.24 228,90.33 227.88,90.51 214.89,92.8 211.14,92.14 209.87,91.26 205.88,90.55 194.6,92.54 180.94,90.13 169.15,92.21 165.28,94.92 159.44,95.95 v8(157.94,96.22) 155.87,96.58 155.73,96.48 155.11,96.59 155.01,96.73 154.48,96.82 154.31,96.7 153.74,96.8 153.62,96.98 153.09,97.07 152.93,96.95 152.35,97.06 152.23,97.22 151.7,97.31 151.54,97.2 150.96,97.3 150.84,97.47 149.48,97.71 148.77,97.58 148.66,97.42 148.13,97.33 147.97,97.44 147.44,97.35 147.32,97.19 146.79,97.09 146.63,97.21 146.1,97.11 145.99,96.95 145.46,96.86 145.3,96.97 144.69,96.86 143.56,96.07 143.28,95.68 142.63,94.74 142.46,93.81 141.96,93.09 141.73,92.86 141.46,92.86 141.45,92.86 140.59,92.86 U1.A20
PE_SLOT2_TX_C_DN<11>: length 101.7
  BOTTOM w0.135: U1.A19 140.59,92.06 142.1,92.06 143.04,92.99 143.28,93.35 144.65,95.3 144.84,95.43 145.58,95.56 145.74,95.45 146.27,95.54 146.39,95.71 146.92,95.8 147.08,95.68 147.61,95.78 147.72,95.94 148.25,96.04 148.42,95.92 148.95,96.01 149.06,96.18 149.65,96.28 150.82,96.07 150.93,95.91 151.46,95.81 151.63,95.93 152.16,95.84 152.27,95.67 152.81,95.58 152.97,95.69 153.5,95.6 153.62,95.44 154.15,95.34 154.31,95.46 154.84,95.36 154.96,95.2 155.49,95.1 155.65,95.22 156.18,95.13 156.3,94.96 156.83,94.87 156.99,94.98 157.52,94.89 157.64,94.72 158.17,94.63 158.33,94.75 158.87,94.65 158.98,94.49 159.51,94.39 159.68,94.51 160.21,94.42 160.32,94.25 160.85,94.16 161.02,94.27 161.55,94.18 161.66,94.01 162.19,93.92 162.36,94.04 v8(163.19,93.89) 164.53,93.65 165,93.57 168.69,90.99 180.82,88.85 194.51,91.27 206.47,89.16 206.49,89.16 206.5,89.15 210.04,89.78 211.59,90.87 215.09,91.48 227.34,89.32 228.62,88.63 228.69,88.38 228.27,87.62 228.44,87.02 228.99,86.72 229.59,86.9 230.04,87.71 230.6,87.88 231.13,87.59 231.7,87.02 231.7,85.46 C122.1
PE_SLOT2_TX_C_DN<12>: length 94.6
  BOTTOM w0.135: C123.1 227.7,85.46 227.7,85.87 226.89,87.22 224.78,88.34 222.77,88.7 222.61,88.58 222.18,88.66 222.07,88.82 221.63,88.9 221.47,88.78 221.04,88.86 220.93,89.02 215.14,90.04 211.77,89.45 209.49,87.85 207.85,87.56 194.31,89.95 180.76,87.56 v8(172.26,89.06) 168.12,89.79 164.56,92.28 160.04,93.08 160.04,93.08 159.86,92.95 159.33,93.05 159.21,93.22 158.68,93.32 158.5,93.19 157.97,93.29 157.84,93.47 157.31,93.56 157.14,93.43 156.61,93.53 156.48,93.71 155.95,93.8 155.77,93.67 155.24,93.77 155.12,93.95 154.59,94.04 154.41,93.92 153.88,94.01 153.75,94.19 153.22,94.28 153.04,94.16 152.51,94.25 152.39,94.43 151.86,94.52 151.68,94.4 151.15,94.49 151.03,94.67 149.63,94.91 149.03,94.81 148.9,94.62 148.36,94.53 148.18,94.66 147.65,94.56 147.52,94.38 146.98,94.28 146.8,94.41 145.82,94.24 144.95,93.63 143.41,91.43 143.28,91.34 142.14,90.54 141.66,90.46 140.59,90.46 U1.A17
PE_SLOT2_TX_C_DN<13>: length 94.8
  BOTTOM w0.135: C124.1 223.72,85.49 223.72,86.29 223.58,86.57 223.16,86.74 222.69,86.64 222.44,86.36 222.44,84.64 222.01,84.21 221.37,84.21 220.94,84.64 220.94,86.67 220.83,87.27 220.55,87.67 220.25,87.88 218.35,88.21 218.18,88.09 217.64,88.19 217.53,88.36 216.99,88.45 216.82,88.33 216.29,88.43 216.17,88.6 215.34,88.74 212.52,88.25 210.46,86.8 207.85,86.34 194.31,88.73 190.63,88.08 v8(190.63,88.08) 190.55,88.06 190.54,88.07 180.76,86.34 167.65,88.65 164.53,90.84 161.98,91.29 161.98,91.28 160.59,91.53 160.48,91.45 159.81,91.57 159.73,91.68 159.2,91.78 159.01,91.64 158.48,91.73 158.34,91.93 157.81,92.02 157.62,91.88 157.08,91.98 156.95,92.17 156.42,92.27 156.22,92.13 155.69,92.22 155.56,92.42 155.03,92.51 154.83,92.38 154.3,92.47 154.17,92.66 153.64,92.76 153.44,92.62 152.91,92.71 152.78,92.91 152.25,93 152.05,92.87 151.52,92.96 151.39,93.15 149.45,93.5 149.15,93.44 149.03,93.27 148.5,93.18 148.33,93.3 147.8,93.21 147.68,93.03 147.15,92.94 146.98,93.06 146.35,92.95 145.65,92.46 144.36,90.62 143.34,89.91 143.28,89.9 141.92,89.66 140.59,89.66 U1.A16
PE_SLOT2_TX_C_DN<14>: length 84.9
  BOTTOM w0.135: C125.1 218.96,85.49 218.96,85.84 218.85,86.45 218.56,86.66 217.92,86.77 217.77,86.66 217.19,86.76 217.08,86.92 216.55,87.01 214.79,87.32 214.42,87.26 213.31,87.06 211.01,85.45 207.52,84.84 205.51,85.18 205.33,85.05 204.8,85.15 204.67,85.33 204.14,85.42 203.96,85.29 203.42,85.38 203.29,85.57 202.76,85.66 202.58,85.53 202.05,85.62 201.92,85.8 201.39,85.89 201.21,85.76 200.67,85.86 200.54,86.04 200.01,86.13 199.83,86 199.3,86.09 199.17,86.28 198.64,86.37 198.45,86.24 197.92,86.33 197.79,86.51 197.47,86.57 194.04,85.96 193.93,85.8 v8(190.07,85.12) 185.17,84.26 167.06,87.45 164.49,89.25 156.59,90.64 156.47,90.56 155.86,90.67 155.78,90.78 155.25,90.88 155.12,90.79 154.53,90.89 154.44,91.02 153.91,91.12 153.75,91 153.22,91.09 153.1,91.26 152.57,91.35 152.41,91.24 151.88,91.33 151.76,91.5 151.23,91.59 151.07,91.47 150.54,91.57 150.42,91.73 149.42,91.91 146.73,91.43 146.08,90.98 145.23,89.76 144.88,89.52 143.41,88.41 143.33,88.39 143.29,88.39 143.28,88.38 141.38,88.05 140.58,88.05 U1.A14
PE_SLOT2_TX_C_DN<15>: length 82.8
  BOTTOM w0.135: C126.1 215.72,85.49 215.72,85.77 215.58,85.94 214.83,86.07 214.05,85.9 213.28,85.35 213.26,85.25 212.76,84.9 212.65,84.92 211.9,84.39 211.16,84.26 211.03,84.24 210.49,84.14 210.37,83.96 209.84,83.87 209.65,83.99 209.12,83.9 209,83.72 208.47,83.62 208.28,83.75 207.75,83.66 207.63,83.48 207.09,83.38 206.91,83.51 206.18,83.38 206.12,83.39 202.34,84.06 202.12,83.9 201.99,83.14 201.62,82.88 201.01,82.99 200.75,83.36 200.89,84.12 200.73,84.34 200.6,84.43 198.9,84.73 196.54,84.31 196.45,84.19 195.84,84.08 195.71,84.17 195.18,84.08 195.09,83.94 194.49,83.84 194.36,83.93 187.23,82.67 185.48,82.98 v8(183.99,83.25) 166.59,86.32 164.29,87.92 157.97,89.03 157.82,88.92 157.29,89.02 157.18,89.17 156.65,89.27 156.49,89.16 155.96,89.25 155.85,89.41 155.32,89.5 155.16,89.39 154.63,89.49 154.52,89.64 153.99,89.74 153.83,89.63 153.3,89.72 153.19,89.88 152.66,89.97 152.51,89.86 151.98,89.95 151.87,90.11 151.34,90.21 151.18,90.09 150.65,90.19 150.54,90.35 149.01,90.62 147.61,90.37 147.05,89.98 146.15,88.69 143.95,87.15 143.45,87.06 143.28,87.09 142.34,87.26 140.59,87.26 U1.A13
PE_SLOT2_TX_C_DP<0>: length 178.2
  BOTTOM w0.089: U1.V22 126.54,94.71 126.54,95.18 126.39,95.33 126.39,96.16 126.34,96.22 126.34,96.24
  BOTTOM w0.135: 126.34,96.24 126.34,96.93 126.06,97.21 126.06,101.68 137.12,112.74 137.13,112.74 140.03,114.77 150.1,116.54 164.2,114.06 168.73,110.89 172.41,105.63 174.54,104.13 180.42,103.1 196.3,105.89 202.91,104.73 216.77,107.17 246.68,101.9 249.15,100.17 264.74,97.42 v8(269.4,94.16) 274.3,90.73 278.86,87.54 279.99,85.92 279.99,85.46 C39.1
PE_SLOT2_TX_C_DP<1>: length 176
  BOTTOM w0.089: 127.25,97.02 127.25,97 127.31,96.95 127.31,94.96 127.69,94.58 U1.U22
  BOTTOM w0.135: C40.1 275.95,85.46 275.95,86.91 275.4,87.68 272.57,89.66 272.06,89.57 271.78,89.17 271.52,89.13 271.3,89.28 271.26,89.54 271.54,89.94 271.45,90.45 271.02,90.75 270.51,90.66 270.23,90.26 269.97,90.21 269.75,90.37 269.7,90.63 269.98,91.03 269.89,91.54 269.47,91.84 268.96,91.75 268.68,91.35 268.41,91.3 268.2,91.46 268.15,91.72 268.43,92.12 268.31,92.78 263.03,96.48 v8(262.46,96.56) 260.2,96.91 248.02,99.06 245.5,100.83 217.06,105.84 202.75,103.32 195.81,104.55 180.48,101.84 174.07,102.97 171.29,104.92 168.71,108.6 162.69,112.81 155.91,114.01 155.91,114.01 149.91,115.07 142.11,113.69 138.58,112.24 127.54,101.19 127.54,97.74 127.25,97.45 127.25,97.02
PE_SLOT2_TX_C_DP<2>: length 164.7
  BOTTOM w0.089: 128.85,97.02 128.85,97 128.91,96.95 128.91,95.46 128.86,95.4 128.86,95.01 129.29,94.58 U1.R22
  BOTTOM w0.135: 128.85,97.02 128.85,100.58 138.34,110.06 140.97,111.91 150.1,113.52 162.61,111.31 167.81,107.67 170.32,104.08 173.73,101.69 180.22,100.55 195.87,103.31 203.26,102.01 217.28,104.48 244.96,99.59 247.98,97.48 252.92,96.61 v8(254.25,96.38) 259.85,95.39 271.5,87.23 271.95,86.7 272.01,86.49 272.01,85.46 C41.1
PE_SLOT2_TX_C_DP<3>: length 162.6
  BOTTOM w0.089: U1.P22 130.09,94.58 129.71,94.96 129.71,96.95 129.65,97 129.65,97.02
  BOTTOM w0.135: 129.65,97.02 129.65,97.45 130.05,97.86 130.05,99.83 135.56,105.33 136.78,105.33 137.38,105.94 139.5,108.96 140.14,109.41 145.81,111.08 v8(147.34,111.53) 149.49,112.17 162.2,109.93 166.74,106.75 169.05,103.45 173.18,100.56 180.35,99.3 195.71,102 203.26,100.67 217.35,103.16 243.44,98.54 246.4,96.46 257.23,94.55 263.65,90.06 263.74,89.58 263.43,89.14 263.47,88.88 263.69,88.73 263.95,88.77 264.26,89.21 264.77,89.3 265.2,89.01 265.29,88.49 264.75,87.72 264.8,87.46 265.02,87.31 265.28,87.35 265.91,88.25 266.62,88.38 267.16,88 267.78,87.11 267.97,86.04 267.97,85.46 C42.1
PE_SLOT2_TX_C_DP<4>: length 145.8
  BOTTOM w0.089: U1.M22 131.69,94.58 131.31,94.95 131.31,96.95 131.26,97 131.26,97.02
  BOTTOM w0.135: 131.26,97.02 131.26,99.12 136.07,103.94 137.24,103.94 138.97,105.67 140.07,105.77 141.18,105.86 143.93,106.11 143.93,106.1 145.17,106.21 145.17,106.21 145.73,106.26 145.74,106.26 147.1,106.38 160.37,104.04 v8(161.8,103.79) 168.02,102.69 172.78,99.35 180.21,98.05 195.02,100.66 203.18,99.22 216.16,101.59 242.92,97.23 246.74,94.75 252.3,93.9 252.3,93.9 252.63,93.85 258.9,90.09 260.88,88.13 261.72,86.69 261.98,86.19 261.98,85.46 C103.1
PE_SLOT2_TX_C_DP<5>: length 145.6
  BOTTOM w0.089: 132.05,97.02 132.05,97 132.11,96.95 132.11,94.96 132.49,94.58 U1.L22
  BOTTOM w0.135: 132.05,97.02 132.05,97.45 132.72,98.12 132.97,98.12 137.27,102.42 139.12,103.71 147.1,105.12 156.05,103.54 v8(157.57,103.27) 167.46,101.53 172.19,98.22 180.23,96.8 195.03,99.41 196.7,99.12 196.7,99.12 198.59,98.79 203.53,97.91 216.22,100.15 239.05,96.12 244.86,94.05 246.67,93.23 247.39,93.01 247.68,92.46 247.25,91.06 247.43,90.73 247.78,90.62 248.11,90.8 248.54,92.2 249.09,92.5 249.69,92.31 249.98,91.76 249.55,90.36 249.73,90.03 250.09,89.92 250.41,90.1 250.84,91.5 251.39,91.8 252.55,91.45 256.61,88.48 257.74,87.35 257.94,86.2 257.94,85.46 C104.1
PE_SLOT2_TX_C_DP<6>: length 131.2
  BOTTOM w0.089: 133.65,96.47 133.65,96.44 133.71,96.39 133.71,94.95 134.09,94.58 U1.J22
  BOTTOM w0.135: C105.1 253.98,85.46 253.98,86.02 253.63,86.51 253.34,86.71 250.08,88.51 248.92,88.71 247.77,88.91 240.4,94.07 239.88,94.29 215.51,98.58 203.72,96.5 194.58,98.11 180.23,95.58 171.71,97.09 167.27,100.2 v8(164.69,100.65) 163.21,100.91 147.24,103.73 144.25,103.2 141.81,102.77 140.7,101.99 139.65,101.81 136.12,98.28 135.15,98.28 133.65,96.78 133.65,96.47
PE_SLOT2_TX_C_DP<7>: length 130.9
  BOTTOM w0.089: U1.H22 134.89,94.58 134.51,94.96 134.51,95.89 135.03,96.41 135.03,96.49 135.05,96.51
  BOTTOM w0.135: C106.1 249.94,85.46 249.94,86.01 249.62,86.33 248.56,86.33 248.09,85.85 248.09,84.33 247.95,84.2 247.34,84.2 247.13,84.4 247.13,86.5 247,86.87 246.36,87.62 246,87.99 242.13,90.69 241.62,90.6 241.33,90.18 241.07,90.13 240.85,90.29 240.8,90.55 241.1,90.97 241.01,91.48 240.24,92.53 238.63,93.18 238.63,93.18 238.51,93.23 233.06,94.19 222.3,96.09 221.16,96.29 215.41,97.3 203.42,95.19 194.72,96.72 180.52,94.22 171.26,95.85 166.95,98.86 v8(157.1,100.6) 155.71,100.85 147.31,102.33 144.11,101.76 143.55,101.76 141.3,100.19 141.17,100.17 140.02,100.17 137.16,97.31 135.85,97.31 135.05,96.51
PE_SLOT2_TX_C_DP<8>: length 112.1
  BOTTOM w0.135: C107.1 244,85.46 244,85.87 243.93,86.31 243.49,86.94 242.47,87.55 241.54,87.72 239.38,89.23 235.07,92.25 214.63,95.85 203.66,93.91 196.54,95.17 195.02,95.43 180.76,92.92 170.66,94.7 166.79,97.41 v8(158.4,98.89) 157.1,99.12 148.05,100.71 143.67,99.94 142.12,98.86 139.98,95.8 139.94,95.58 139.94,95.42 U1.B23
PE_SLOT2_TX_C_DP<9>: length 111.8
  BOTTOM w0.135: C108.1 240,85.46 240,85.97 239.69,86.28 238.52,86.28 238.21,85.97 238.21,84.71 238.07,84.57 237.45,84.57 237.31,84.71 237.31,87.52 237.21,88.1 236.57,89.01 236.54,89.06 233.38,91.26 217.67,94.04 217.67,94.03 215.03,94.5 214.87,94.47 214.87,94.47 210.45,93.69 209.06,92.72 206.12,92.2 197.83,93.66 195.05,94.15 180.94,91.66 169.73,93.64 165.87,96.35 v8(154.85,98.29) 153.44,98.54 149.08,99.31 148.37,99.18 144.37,98.48 143.28,97.72 142.72,97.32 140.93,94.76 140.33,94.76 139.93,94.36 U1.B22
PE_SLOT2_TX_C_DP<10>: length 103.8
  BOTTOM w0.135: U1.B20 139.93,92.76 140.33,93.16 141.32,93.16 141.33,93.17 141.61,93.17 141.73,93.29 142.17,93.93 142.34,94.86 143.28,96.21 143.34,96.29 144.57,97.15 149.48,98.02 157.99,96.52 v8(159.49,96.25) 165.4,95.21 169.27,92.5 180.94,90.44 194.6,92.85 205.88,90.86 209.75,91.55 210.02,91.74 211.02,92.43 214.89,93.11 232.32,90.04 234.44,88.55 234.88,87.94 235.1,86.67 234.99,86.04 234.99,85.32 235.2,85.11 C109.1
PE_SLOT2_TX_C_DP<11>: length 101.7
  BOTTOM w0.135: C110.1 232,85.46 232,87.15 231.31,87.84 230.64,88.21 229.83,87.97 229.38,87.16 229.03,87.05 228.7,87.23 228.6,87.59 229.01,88.35 228.87,88.83 227.45,89.61 221.27,90.7 215.09,91.79 211.47,91.15 209.92,90.07 206.5,89.46 194.51,91.58 180.82,89.16 168.8,91.28 165.12,93.86 v8(164.58,93.96) 163.24,94.19 149.65,96.59 144.72,95.72 144.44,95.52 143.28,93.88 142.8,93.19 141.97,92.36 140.33,92.36 139.93,91.96 U1.B19
PE_SLOT2_TX_C_DP<12>: length 94.7
  BOTTOM w0.135: C111.1 228,85.46 228,85.95 227.11,87.45 224.88,88.63 215.14,90.35 211.65,89.74 209.37,88.14 207.85,87.87 194.31,90.26 180.76,87.87 v8(174.05,89.05) 172.32,89.36 168.24,90.08 164.68,92.57 160.1,93.38 160.09,93.38 149.63,95.22 145.7,94.53 144.73,93.85 143.28,91.79 143.19,91.65 142.02,90.83 141.63,90.76 140.33,90.76 139.93,90.36 U1.B17
PE_SLOT2_TX_C_DP<13>: length 94.8
  BOTTOM w0.135: U1.B16 139.93,89.56 140.33,89.96 141.89,89.96 143.22,90.2 143.28,90.24 144.14,90.84 145.43,92.67 146.23,93.24 146.92,93.36 149.45,93.81 164.65,91.13 167.77,88.94 180.76,86.65 190.5,88.37 v8(191.93,88.62) 194.31,89.04 207.85,86.65 210.34,87.09 212.4,88.54 215.34,89.05 219.49,88.32 220.37,88.17 220.77,87.88 220.94,87.64 220.94,87.64 221.12,87.39 221.24,86.7 221.24,84.76 221.49,84.51 221.88,84.51 222.14,84.76 222.14,86.48 222.53,86.92 223.19,87.06 223.8,86.81 224.03,86.37 224.03,85.44 C112.1
PE_SLOT2_TX_C_DP<14>: length 84.8
  BOTTOM w0.135: U1.B14 139.93,87.96 140.32,88.35 141.35,88.35 143.23,88.68 143.28,88.69 143.28,88.7 144.71,89.77 145.01,89.98 145.86,91.2 146.61,91.72 149.42,92.22 164.61,89.54 167.18,87.74 185.17,84.57 190.01,85.42 v8(191.48,85.68) 193.75,86.08 193.86,86.24 197.47,86.88 207.52,85.15 210.89,85.74 213.19,87.35 214.79,87.63 218.68,86.95 219.03,86.7 219.13,86.63 219.27,85.87 219.27,85.44 C113.1
PE_SLOT2_TX_C_DP<15>: length 82.8
  BOTTOM w0.135: C114.1 216.03,85.44 216.03,85.88 215.74,86.22 214.82,86.38 213.93,86.18 211.78,84.68 211.11,84.56 211.11,84.56 206.18,83.69 202.27,84.38 201.84,84.08 201.71,83.32 201.55,83.21 201.18,83.27 201.07,83.43 201.21,84.19 200.91,84.62 200.72,84.72 198.9,85.04 187.23,82.98 v8(185.53,83.28) 184.05,83.55 166.71,86.6 164.41,88.21 149.01,90.93 147.49,90.66 146.83,90.2 145.93,88.91 143.83,87.44 143.45,87.37 143.28,87.4 142.91,87.47 142.37,87.56 140.33,87.56 139.93,87.16 U1.B13
PE_SLOT2_TX_DN<0>: length 6.4
  BOTTOM w0.135: C43.2 279.68,83.95 279.68,79.68 279.95,79.41 280.14,79.32 280.14,79.32 280.2,79.14 J2.B15
PE_SLOT2_TX_DN<1>: length 6.3
  BOTTOM w0.135: C44.2 275.64,83.95 275.64,83.55 275.49,83.4 275.49,82.99 275.64,82.84 275.64,82.44 275.49,82.28 275.49,81.88 275.64,81.73 275.64,79.76 275.54,79.65 275.4,79.58 275.2,79.65 J2.B20
PE_SLOT2_TX_DN<2>: length 6.3
  BOTTOM w0.135: J2.B24 271.2,79.65 271.38,79.59 271.5,79.65 271.73,79.88 271.73,81.7 271.58,81.85 271.58,82.26 271.73,82.41 271.73,82.81 271.58,82.97 271.58,83.37 271.73,83.52 271.73,83.93 C45.2
PE_SLOT2_TX_DN<3>: length 6.3
  BOTTOM w0.135: J2.B28 267.2,79.65 267.39,79.59 267.51,79.65 267.67,79.81 267.67,81.73 267.51,81.88 267.51,82.28 267.67,82.44 267.67,82.84 267.51,82.99 267.51,83.4 267.67,83.55 267.67,83.95 C46.2
PE_SLOT2_TX_DN<4>: length 6.3
  BOTTOM w0.135: J2.B34 261.2,79.65 261.38,79.59 261.53,79.67 261.67,79.81 261.67,81.73 261.52,81.88 261.52,82.28 261.67,82.44 261.67,82.84 261.52,82.99 261.52,83.4 261.67,83.55 261.67,83.95 C115.2
PE_SLOT2_TX_DN<5>: length 6.3
  BOTTOM w0.135: C116.2 257.68,83.9 257.68,83.5 257.53,83.35 257.53,82.94 257.68,82.79 257.68,82.38 257.53,82.23 257.53,81.83 257.68,81.67 257.68,79.81 257.58,79.7 257.37,79.6 257.2,79.65 J2.B38
PE_SLOT2_TX_DN<6>: length 6.3
  BOTTOM w0.135: C117.2 253.67,83.95 253.67,83.55 253.52,83.4 253.52,82.99 253.67,82.84 253.67,82.44 253.52,82.28 253.52,81.88 253.67,81.73 253.67,79.8 253.54,79.66 253.39,79.59 253.2,79.65 J2.B42
PE_SLOT2_TX_DN<7>: length 6.3
  BOTTOM w0.135: C118.2 249.63,83.95 249.63,83.55 249.48,83.4 249.48,82.99 249.63,82.84 249.63,82.44 249.48,82.28 249.48,81.88 249.63,81.73 249.63,79.78 249.51,79.65 249.38,79.59 249.2,79.65 J2.B46
PE_SLOT2_TX_DN<8>: length 6.4
  BOTTOM w0.135: C119.2 243.69,83.97 243.69,79.68 243.96,79.41 244.14,79.32 244.2,79.14 J2.B51
PE_SLOT2_TX_DN<9>: length 6.4
  BOTTOM w0.135: C120.2 239.69,83.97 239.69,79.68 239.96,79.41 240.14,79.32 240.2,79.14 J2.B55
PE_SLOT2_TX_DN<10>: length 6.7
  BOTTOM w0.135: C121.2 234.67,83.97 234.67,82.38 235.69,80.5 235.69,79.68 235.96,79.41 236.14,79.32 236.25,78.99 J2.B59
PE_SLOT2_TX_DN<11>: length 6.4
  BOTTOM w0.135: J2.B63 232.22,78.96 232.12,79.24 231.69,79.68 231.69,83.97 C122.2
PE_SLOT2_TX_DN<12>: length 6.4
  BOTTOM w0.135: C123.2 227.69,83.97 227.69,79.68 227.96,79.41 228.14,79.32 228.25,78.99 J2.B67
PE_SLOT2_TX_DN<13>: length 6.4
  BOTTOM w0.135: J2.B71 224.2,79.14 224.14,79.32 223.96,79.41 223.69,79.68 223.69,83.97 C124.2
PE_SLOT2_TX_DN<14>: length 6.6
  BOTTOM w0.135: J2.B75 220.2,79.14 220.14,79.32 219.96,79.41 219.69,79.68 219.69,80.56 219.58,80.95 218.92,82.19 218.92,83.97 C125.2
PE_SLOT2_TX_DN<15>: length 6.4
  BOTTOM w0.135: J2.B79 216.2,79.14 216.14,79.32 215.96,79.41 215.69,79.68 215.69,83.97 C126.2
